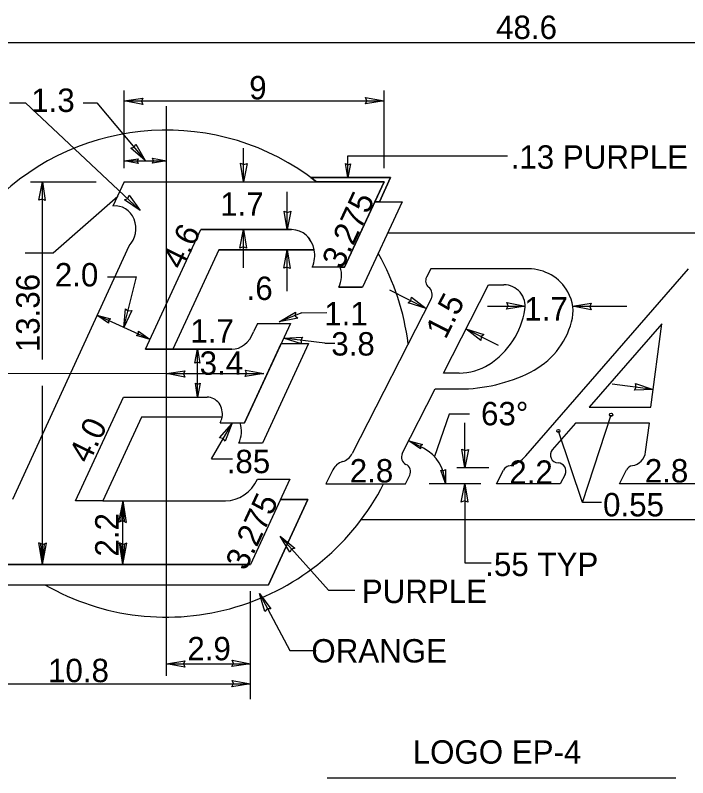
# Model space of a CAD drawing. Extents: x 10268197 to 10269179, y 2141503 to 2142677.
# Drawn here: x 10268476.2 to 10268496.32, y 2142043.07 to 2142065.9 of the extents above; entities that cross this region are included whole.
import ezdxf

# ---------------------------------------------------------------- set-up
doc = ezdxf.new("R2010")
doc.units = 0
for name, color, linetype in [('1', 7, 'Continuous'), ('2', 7, 'Continuous'), ('21', 7, 'Continuous'), ('3', 7, 'Continuous'), ('52', 7, 'Continuous')]:
    doc.layers.add(name, color=color, linetype=linetype)

msp = doc.modelspace()

# ---------------------------------------------------------------- linework, layer by layer
at = {"layer": '1'}
for p, q in [((10268471.492, 2142065.08), (10268513.188, 2142065.08)), ((10268479.456, 2142061.321), (10268479.456, 2142063.644)), ((10268487.229, 2142061.321), (10268487.229, 2142063.644)), ((10268478.224, 2142063.27), (10268478.635, 2142063.27)), ((10268478.635, 2142063.27), (10268480.081, 2142061.551)), ((10268479.456, 2142063.33), (10268487.229, 2142063.33)), ((10268480.718, 2142055.17), (10268480.718, 2142063.176)), ((10268483.026, 2142060.91), (10268483.026, 2142061.916)), ((10268486.145, 2142061.037), (10268486.145, 2142061.684)), ((10268486.145, 2142061.684), (10268490.92, 2142061.684)), ((10268479.456, 2142061.537), (10268480.718, 2142061.537)), ((10268476.655, 2142060.91), (10268478.617, 2142060.91)), ((10268477.008, 2142055.592), (10268477.008, 2142060.91)), ((10268485.209, 2142060.91), (10268485.042, 2142061.037)), ((10268485.042, 2142061.037), (10268487.426, 2142061.037)), ((10268487.229, 2142060.91), (10268485.209, 2142060.91)), ((10268486.951, 2142060.308), (10268487.229, 2142060.91)), ((10268487.426, 2142061.037), (10268487.09, 2142060.308)), ((10268477.329, 2142058.782), (10268479.262, 2142060.483)), ((10268484.333, 2142059.479), (10268484.333, 2142060.61)), ((10268486.051, 2142058.36), (10268486.951, 2142060.308)), ((10268487.768, 2142060.308), (10268486.589, 2142057.756)), ((10268486.951, 2142060.308), (10268487.768, 2142060.308)), ((10268486.951, 2142060.308), (10268487.768, 2142060.308)), ((10268487.09, 2142060.308), (10268486.951, 2142060.308)), ((10268480.096, 2142055.898), (10268481.749, 2142059.479)), ((10268481.749, 2142059.479), (10268484.466, 2142059.479)), ((10268483.026, 2142058.333), (10268483.026, 2142059.479)), ((10268482.289, 2142058.875), (10268480.913, 2142055.898)), ((10268482.289, 2142058.875), (10268485.144, 2142058.875)), ((10268485.144, 2142058.875), (10268482.799, 2142058.875)), ((10268484.333, 2142057.633), (10268484.333, 2142058.875)), ((10268476.495, 2142058.782), (10268477.329, 2142058.782)), ((10268485.92, 2142058.36), (10268486.051, 2142058.36)), ((10268478.956, 2142058.062), (10268479.82, 2142058.062)), ((10268479.449, 2142056.551), (10268479.82, 2142058.062)), ((10268486.589, 2142057.756), (10268485.878, 2142057.756)), ((10268487.392, 2142057.676), (10268488.491, 2142057.116)), ((10268490.325, 2142057.188), (10268491.454, 2142057.188)), ((10268492.873, 2142057.188), (10268494.498, 2142057.188)), ((10268480.231, 2142056.19), (10268478.642, 2142056.923)), ((10268484.773, 2142056.991), (10268484.093, 2142056.721)), ((10268484.773, 2142056.991), (10268485.516, 2142056.995)), ((10268489.68, 2142056.512), (10268490.642, 2142056.022)), ((10268485.463, 2142056.078), (10268484.226, 2142056.23)), ((10268480.913, 2142055.898), (10268480.096, 2142055.898)), ((10268481.651, 2142054.467), (10268481.651, 2142055.898)), ((10268483.055, 2142053.693), (10268484.151, 2142056.069)), ((10268484.969, 2142056.069), (10268483.595, 2142053.092)), ((10268484.151, 2142056.069), (10268484.969, 2142056.069)), ((10268485.463, 2142056.078), (10268485.758, 2142056.079)), ((10268480.718, 2142055.17), (10268473.43, 2142055.159)), ((10268480.718, 2142046.13), (10268480.718, 2142055.17)), ((10268480.718, 2142055.17), (10268483.634, 2142055.17)), ((10268477.008, 2142049.457), (10268477.008, 2142054.809)), ((10268495.286, 2142054.695), (10268494.056, 2142054.855)), ((10268478.002, 2142051.365), (10268479.434, 2142054.467)), ((10268479.434, 2142054.467), (10268481.941, 2142054.467)), ((10268479.976, 2142053.864), (10268478.819, 2142051.365)), ((10268482.386, 2142053.864), (10268479.976, 2142053.864)), ((10268489.174, 2142053.958), (10268488.742, 2142052.685)), ((10268489.786, 2142053.958), (10268489.174, 2142053.958)), ((10268493.165, 2142051.313), (10268494.024, 2142053.938)), ((10268482.072, 2142052.621), (10268482.678, 2142053.67)), ((10268482.927, 2142053.693), (10268483.055, 2142053.693)), ((10268489.645, 2142052.351), (10268489.645, 2142053.693)), ((10268493.165, 2142051.313), (10268492.445, 2142053.451)), ((10268488.408, 2142052.937), (10268487.971, 2142053.161)), ((10268483.595, 2142053.092), (10268482.883, 2142053.092)), ((10268482.072, 2142052.621), (10268482.694, 2142052.621)), ((10268490.361, 2142052.351), (10268489.407, 2142052.351)), ((10268490.122, 2142051.875), (10268488.583, 2142051.875)), ((10268489.645, 2142051.875), (10268489.645, 2142049.507)), ((10268478.819, 2142051.365), (10268478.002, 2142051.365)), ((10268479.414, 2142049.457), (10268479.414, 2142051.365)), ((10268484.136, 2142051.405), (10268483.237, 2142049.457)), ((10268483.775, 2142048.853), (10268484.954, 2142051.405)), ((10268484.954, 2142051.405), (10268484.136, 2142051.405)), ((10268493.736, 2142051.313), (10268493.165, 2142051.313)), ((10268484.123, 2142050.306), (10268485.564, 2142048.69)), ((10268489.645, 2142049.507), (10268490.439, 2142049.507)), ((10268483.237, 2142049.457), (10268475.399, 2142049.457)), ((10268475.12, 2142048.853), (10268483.775, 2142048.853)), ((10268483.237, 2142045.422), (10268483.237, 2142048.664)), ((10268483.5, 2142048.585), (10268484.407, 2142046.88)), ((10268485.564, 2142048.69), (10268486.357, 2142048.69)), ((10268484.407, 2142046.88), (10268485.2, 2142046.88)), ((10268480.718, 2142046.489), (10268483.237, 2142046.489)), ((10268474.003, 2142045.883), (10268483.237, 2142045.883))]:
    msp.add_line(p, q, dxfattribs=at)
msp.add_lwpolyline([(10268476.022, 2142063.273), (10268476.5, 2142063.273), (10268479.932, 2142060.051)], dxfattribs=at)
msp.add_lwpolyline([(10268485.042, 2142061.037), (10268485.209, 2142060.91), (10268487.229, 2142060.91), (10268486.951, 2142060.308), (10268487.09, 2142060.308), (10268487.426, 2142061.037)], close=True, dxfattribs=at)
for centre in [(10268494.023, 2142053.938), (10268492.445, 2142053.451)]:
    msp.add_circle(centre, 0.0476, dxfattribs=at)
msp.add_arc((10268487.868, 2142051.876), 1.191, 0, 62.9941, dxfattribs=at)
for centre, major_axis, start_param, end_param in [((10268484.466, 2142058.715), (0, 0.764), 4.924772, 6.283185), ((10268485.266, 2142058.112), (0, 0.764), 4.227342, 5.041732), ((10268481.94, 2142053.965), (0, 0.502), 4.510784, 6.283185), ((10268482.271, 2142053.448), (0, 0.764), 4.227342, 5.041732)]:
    msp.add_ellipse(centre, major_axis=major_axis, ratio=0.906667, start_param=start_param, end_param=end_param, dxfattribs=at)
at = {"layer": '2'}
for p, q in [((10268479.456, 2142060.91), (10268479.12, 2142060.181)), ((10268479.456, 2142060.91), (10268487.229, 2142060.91)), ((10268485.042, 2142061.037), (10268487.426, 2142061.037)), ((10268487.229, 2142060.91), (10268486.051, 2142058.36)), ((10268487.426, 2142061.037), (10268487.09, 2142060.308)), ((10268487.768, 2142060.308), (10268486.589, 2142057.756)), ((10268486.951, 2142060.308), (10268487.768, 2142060.308)), ((10268480.096, 2142055.898), (10268481.749, 2142059.479)), ((10268481.749, 2142059.479), (10268484.466, 2142059.479)), ((10268513.188, 2142059.378), (10268487.339, 2142059.378)), ((10268476.127, 2142051.417), (10268479.601, 2142058.998)), ((10268482.289, 2142058.875), (10268480.913, 2142055.898)), ((10268485.144, 2142058.875), (10268482.289, 2142058.875)), ((10268486.051, 2142058.36), (10268485.078, 2142058.36)), ((10268488.63, 2142058.307), (10268488.5, 2142058.052)), ((10268491.548, 2142058.307), (10268488.63, 2142058.307)), ((10268491.475, 2142052.711), (10268496.34, 2142058.307)), ((10268485.878, 2142057.756), (10268486.589, 2142057.756)), ((10268489.004, 2142055.187), (10268490.352, 2142057.831)), ((10268489.004, 2142055.187), (10268490.352, 2142057.83)), ((10268490.352, 2142057.831), (10268490.811, 2142057.831)), ((10268490.352, 2142057.83), (10268490.811, 2142057.83)), ((10268488.638, 2142057.407), (10268486.28, 2142052.777)), ((10268484.43, 2142056.672), (10268483.055, 2142053.693)), ((10268483.444, 2142056.672), (10268483.327, 2142056.419)), ((10268483.444, 2142056.672), (10268484.43, 2142056.672)), ((10268495.543, 2142056.664), (10268493.367, 2142054.162)), ((10268495.543, 2142056.663), (10268493.367, 2142054.162)), ((10268495.216, 2142054.162), (10268495.543, 2142056.664)), ((10268495.216, 2142054.162), (10268495.543, 2142056.663)), ((10268480.096, 2142055.898), (10268482.676, 2142055.898)), ((10268482.676, 2142055.898), (10268480.096, 2142055.898)), ((10268484.969, 2142056.069), (10268483.595, 2142053.092)), ((10268484.151, 2142056.069), (10268484.969, 2142056.069)), ((10268489.476, 2142055.187), (10268489.004, 2142055.187)), ((10268489.476, 2142055.187), (10268489.004, 2142055.187)), ((10268487.776, 2142052.777), (10268488.761, 2142054.71)), ((10268488.761, 2142054.71), (10268489.476, 2142054.71)), ((10268478.002, 2142051.365), (10268479.434, 2142054.467)), ((10268479.434, 2142054.467), (10268481.941, 2142054.467)), ((10268493.367, 2142054.162), (10268495.216, 2142054.162)), ((10268493.367, 2142054.162), (10268495.216, 2142054.162)), ((10268479.976, 2142053.864), (10268478.819, 2142051.365)), ((10268482.386, 2142053.864), (10268479.976, 2142053.864)), ((10268482.323, 2142053.693), (10268483.055, 2142053.693)), ((10268492.955, 2142053.684), (10268492.264, 2142052.891)), ((10268495.167, 2142053.684), (10268492.955, 2142053.684)), ((10268495.054, 2142052.825), (10268495.167, 2142053.684)), ((10268483.595, 2142053.092), (10268482.883, 2142053.092)), ((10268485.7, 2142052.295), (10268485.487, 2142051.874)), ((10268490.598, 2142051.874), (10268490.805, 2142052.283)), ((10268494.274, 2142051.874), (10268494.485, 2142052.288)), ((10268484.416, 2142052.008), (10268483.237, 2142049.457)), ((10268483.444, 2142052.008), (10268484.416, 2142052.008)), ((10268487.868, 2142051.874), (10268487.997, 2142052.129)), ((10268492.645, 2142052.15), (10268492.504, 2142051.874)), ((10268485.487, 2142051.874), (10268487.868, 2142051.874)), ((10268492.504, 2142051.874), (10268490.598, 2142051.874)), ((10268496.656, 2142051.874), (10268494.274, 2142051.874)), ((10268478.819, 2142051.365), (10268478.002, 2142051.365)), ((10268478.819, 2142051.365), (10268482.483, 2142051.365)), ((10268484.954, 2142051.405), (10268483.775, 2142048.853)), ((10268484.136, 2142051.405), (10268484.954, 2142051.405)), ((10268486.553, 2142050.803), (10268508.819, 2142050.803)), ((10268473.977, 2142049.457), (10268483.237, 2142049.457)), ((10268475.12, 2142048.853), (10268483.775, 2142048.853))]:
    msp.add_line(p, q, dxfattribs=at)
for centre, radius, start, end in [((10268480.718, 2142055.17), 7.288, 51.9618, 218.2529), ((10268480.718, 2142055.17), 7.288, 7.0123, 29.4243), ((10268491.548, 2142056.949), 1.358, 29.4315, 90), ((10268488.712, 2142057.944), 0.238, 152.9784, 231.1602), ((10268488.383, 2142057.536), 0.286, 333.0027, 51.1602), ((10268490.81, 2142057.187), 0.643, 351.076, 90), ((10268490.81, 2142057.187), 0.643, 351.076, 90), ((10268491.693, 2142057.03), 1.191, 344.7074, 29.4315), ((10268489.093, 2142057.457), 2.382, 302.4206, 351.076), ((10268489.093, 2142057.457), 2.382, 302.4206, 351.076), ((10268490.544, 2142057.345), 2.382, 296.6431, 344.7074), ((10268489.476, 2142056.853), 1.667, 270, 302.4206), ((10268489.476, 2142056.854), 1.667, 270, 302.4206), ((10268489.476, 2142059.474), 4.764, 270, 296.6431), ((10268485.855, 2142052.993), 0.476, 286.4317, 332.9959), ((10268487.988, 2142052.669), 0.238, 152.9884, 244.7832), ((10268490.756, 2142053.336), 0.953, 282.7162, 318.9966), ((10268492.443, 2142052.735), 0.238, 138.9824, 268.6869), ((10268494.582, 2142052.886), 0.476, 279.2397, 352.5632), ((10268486.125, 2142052.079), 0.476, 106.4317, 152.9742), ((10268487.785, 2142052.238), 0.238, 333.0239, 64.7832), ((10268492.432, 2142052.259), 0.238, 332.9784, 88.6869), ((10268491.018, 2142052.174), 0.238, 102.7162, 153.0239), ((10268494.697, 2142052.18), 0.238, 99.2397, 153.0239), ((10268480.718, 2142055.17), 7.288, 240.0889, 333.1198)]:
    msp.add_arc(centre, radius, start, end, dxfattribs=at)
for centre, major_axis, ratio, start_param, end_param in [((10268479.2, 2142059.508), (0, 0.68), 0.889671, 3.865417, 6.41824), ((10268484.466, 2142058.715), (0, 0.764), 0.906667, 4.924065, 6.283185), ((10268484.466, 2142058.715), (0, 0.764), 0.906667, 4.924772, 6.283185), ((10268484.466, 2142058.715), (0, 0.764), 0.906667, 4.228038, 4.924065), ((10268485.266, 2142058.112), (0, 0.764), 0.906667, 4.227342, 5.041732), ((10268482.676, 2142056.854), (0, 0.955), 0.764971, 3.141593, 4.241405), ((10268481.94, 2142053.965), (0, 0.502), 0.906667, 4.510784, 6.283185), ((10268481.94, 2142053.965), (0, 0.502), 0.906667, 4.144801, 4.510784), ((10268482.271, 2142053.448), (0, 0.764), 0.906667, 4.227342, 5.041732), ((10268482.483, 2142052.558), (0, 1.193), 0.906667, 3.141593, 4.233038)]:
    msp.add_ellipse(centre, major_axis=major_axis, ratio=ratio, start_param=start_param, end_param=end_param, dxfattribs=at)
at = {"layer": '21'}
msp.add_line((10268485.53, 2142043.075), (10268495.961, 2142043.075), dxfattribs=at)
at = {"layer": '3'}
for p, q in [((10268480.096, 2142055.898), (10268481.749, 2142059.479)), ((10268481.749, 2142059.479), (10268484.466, 2142059.479)), ((10268481.749, 2142059.479), (10268484.466, 2142059.479)), ((10268482.259, 2142059.479), (10268481.749, 2142059.479)), ((10268484.466, 2142059.479), (10268482.259, 2142059.479)), ((10268482.289, 2142058.875), (10268480.913, 2142055.898)), ((10268485.144, 2142058.875), (10268482.289, 2142058.875)), ((10268480.096, 2142055.898), (10268482.676, 2142055.898)), ((10268482.676, 2142055.898), (10268480.096, 2142055.898)), ((10268480.607, 2142055.898), (10268481.425, 2142055.898))]:
    msp.add_line(p, q, dxfattribs=at)
msp.add_ellipse((10268484.466, 2142058.715), major_axis=(0, 0.764), ratio=0.906667, start_param=4.924772, end_param=6.283185, dxfattribs=at)
at = {"layer": '52'}
for p, q in [((10268479.414, 2142051.365), (10268479.288, 2142050.722)), ((10268479.414, 2142051.365), (10268479.349, 2142050.747)), ((10268479.414, 2142051.365), (10268479.516, 2142050.718)), ((10268479.414, 2142051.365), (10268479.457, 2142050.746)), ((10268479.288, 2142050.722), (10268479.403, 2142050.77)), ((10268479.403, 2142050.77), (10268479.516, 2142050.718)), ((10268477.008, 2142049.457), (10268476.905, 2142050.103)), ((10268477.017, 2142050.052), (10268476.905, 2142050.103)), ((10268477.008, 2142049.457), (10268476.964, 2142050.076)), ((10268477.008, 2142049.457), (10268477.132, 2142050.099)), ((10268477.008, 2142049.457), (10268477.072, 2142050.074)), ((10268477.132, 2142050.099), (10268477.017, 2142050.052)), ((10268479.414, 2142049.457), (10268479.311, 2142050.103)), ((10268479.423, 2142050.052), (10268479.311, 2142050.103)), ((10268479.414, 2142049.457), (10268479.37, 2142050.076)), ((10268479.414, 2142049.457), (10268479.538, 2142050.099)), ((10268479.414, 2142049.457), (10268479.478, 2142050.074)), ((10268479.538, 2142050.099), (10268479.423, 2142050.052))]:
    msp.add_line(p, q, dxfattribs=at)
for points in [[(10268479.456, 2142063.33), (10268480.012, 2142063.418), (10268479.971, 2142063.323), (10268480.009, 2142063.224)], [(10268487.229, 2142063.33), (10268486.673, 2142063.243), (10268486.715, 2142063.338), (10268486.677, 2142063.437)], [(10268480.081, 2142061.551), (10268479.656, 2142061.92), (10268479.756, 2142061.949), (10268479.807, 2142062.042)], [(10268479.456, 2142061.537), (10268479.873, 2142061.602), (10268479.842, 2142061.531), (10268479.87, 2142061.457)], [(10268480.718, 2142061.537), (10268480.3, 2142061.471), (10268480.332, 2142061.542), (10268480.304, 2142061.617)], [(10268483.026, 2142060.91), (10268482.939, 2142061.467), (10268483.034, 2142061.425), (10268483.133, 2142061.463)], [(10268486.145, 2142061.037), (10268486.079, 2142061.454), (10268486.151, 2142061.423), (10268486.225, 2142061.452)], [(10268477.008, 2142060.91), (10268477.095, 2142060.354), (10268477, 2142060.396), (10268476.901, 2142060.357)], [(10268479.932, 2142060.051), (10268479.466, 2142060.368), (10268479.562, 2142060.409), (10268479.602, 2142060.507)], [(10268484.333, 2142059.479), (10268484.246, 2142060.035), (10268484.341, 2142059.993), (10268484.44, 2142060.032)], [(10268483.026, 2142059.479), (10268483.114, 2142058.922), (10268483.019, 2142058.964), (10268482.919, 2142058.926)], [(10268484.333, 2142058.875), (10268484.421, 2142058.319), (10268484.326, 2142058.361), (10268484.227, 2142058.323)], [(10268488.491, 2142057.116), (10268487.955, 2142057.291), (10268488.035, 2142057.357), (10268488.047, 2142057.462)], [(10268491.454, 2142057.188), (10268490.898, 2142057.1), (10268490.94, 2142057.195), (10268490.901, 2142057.294)], [(10268492.873, 2142057.188), (10268493.429, 2142057.275), (10268493.388, 2142057.18), (10268493.425, 2142057.081)], [(10268479.449, 2142056.551), (10268479.496, 2142057.113), (10268479.579, 2142057.049), (10268479.685, 2142057.063)], [(10268478.642, 2142056.923), (10268479.049, 2142056.808), (10268478.99, 2142056.756), (10268478.985, 2142056.677)], [(10268484.093, 2142056.721), (10268484.577, 2142057.008), (10268484.574, 2142056.903), (10268484.646, 2142056.826)], [(10268480.231, 2142056.19), (10268479.824, 2142056.306), (10268479.883, 2142056.357), (10268479.888, 2142056.437)], [(10268489.68, 2142056.512), (10268490.215, 2142056.337), (10268490.135, 2142056.272), (10268490.123, 2142056.166)], [(10268484.226, 2142056.23), (10268484.788, 2142056.258), (10268484.737, 2142056.167), (10268484.764, 2142056.065)], [(10268481.651, 2142055.898), (10268481.717, 2142055.48), (10268481.645, 2142055.512), (10268481.571, 2142055.483)], [(10268480.718, 2142055.17), (10268481.275, 2142055.258), (10268481.233, 2142055.163), (10268481.271, 2142055.063)], [(10268483.634, 2142055.17), (10268483.078, 2142055.083), (10268483.12, 2142055.178), (10268483.082, 2142055.277)], [(10268481.651, 2142054.467), (10268481.585, 2142054.884), (10268481.657, 2142054.853), (10268481.731, 2142054.881)], [(10268495.286, 2142054.695), (10268494.723, 2142054.679), (10268494.777, 2142054.769), (10268494.752, 2142054.872)], [(10268482.678, 2142053.67), (10268482.475, 2142053.145), (10268482.413, 2142053.229), (10268482.309, 2142053.245)], [(10268487.973, 2142053.154), (10268488.382, 2142053.049), (10268488.324, 2142052.995), (10268488.321, 2142052.916)], [(10268489.645, 2142052.351), (10268489.558, 2142052.908), (10268489.653, 2142052.866), (10268489.752, 2142052.904)], [(10268489.064, 2142051.879), (10268488.924, 2142052.277), (10268488.999, 2142052.259), (10268489.068, 2142052.3)], [(10268489.645, 2142051.875), (10268489.733, 2142051.319), (10268489.638, 2142051.361), (10268489.539, 2142051.323)], [(10268484.123, 2142050.306), (10268484.559, 2142049.949), (10268484.46, 2142049.917), (10268484.411, 2142049.822)], [(10268483.5, 2142048.585), (10268483.839, 2142048.135), (10268483.735, 2142048.128), (10268483.665, 2142048.048)], [(10268480.718, 2142046.489), (10268481.275, 2142046.577), (10268481.233, 2142046.482), (10268481.271, 2142046.382)], [(10268483.237, 2142046.489), (10268482.68, 2142046.402), (10268482.722, 2142046.497), (10268482.684, 2142046.596)], [(10268483.237, 2142045.883), (10268482.68, 2142045.796), (10268482.722, 2142045.891), (10268482.684, 2142045.99)]]:
    msp.add_lwpolyline(points, close=True, dxfattribs=at)

# ---------------------------------------------------------------- texts
at = {"layer": '1'}
for s, p in [('48.6', (10268490.582, 2142065.185)), ('9', (10268483.197, 2142063.378)), ('1.3', (10268476.675, 2142063.002)), ('.13 PURPLE', (10268491.019, 2142061.303)), ('1.7', (10268482.328, 2142059.895)), ('2.0', (10268477.381, 2142057.78)), ('.6', (10268483.118, 2142057.374)), ('1.1', (10268485.441, 2142056.614)), ('1.7', (10268491.425, 2142056.759)), ('1.7', (10268481.438, 2142056.099)), ('3.8', (10268485.652, 2142055.711)), ('3.4', (10268481.713, 2142055.135)), ('63°', (10268490.132, 2142053.623)), ('.85', (10268482.523, 2142052.19)), ('2.8', (10268486.204, 2142051.912)), ('2.2', (10268490.977, 2142051.872)), ('2.8', (10268495.031, 2142051.912)), ('0.55', (10268493.783, 2142050.898)), ('.55 TYP', (10268490.258, 2142049.113)), ('PURPLE', (10268486.565, 2142048.303)), ('2.9', (10268481.345, 2142046.59)), ('ORANGE', (10268485.056, 2142046.524)), ('10.8', (10268477.178, 2142045.935)), ('LOGO EP-4', (10268488.087, 2142043.496))]:
    msp.add_text(s, height=0.7, dxfattribs=at).set_placement(p)
for s, rotation, p in [('3.275', 65.0602, (10268485.976, 2142058.27)), ('4.6', 64.0244, (10268481.189, 2142058.249)), ('13.36', 90, (10268476.924, 2142055.812)), ('1.5', 62.9907, (10268489.07, 2142056.174)), ('4.0', 64.0244, (10268478.396, 2142052.448)), ('3.275', 65.0602, (10268483.093, 2142049.243)), ('2.2', 90, (10268479.287, 2142049.695))]:
    msp.add_text(s, height=0.7, rotation=rotation, dxfattribs=at).set_placement(p)

doc.saveas('drawing.dxf')
